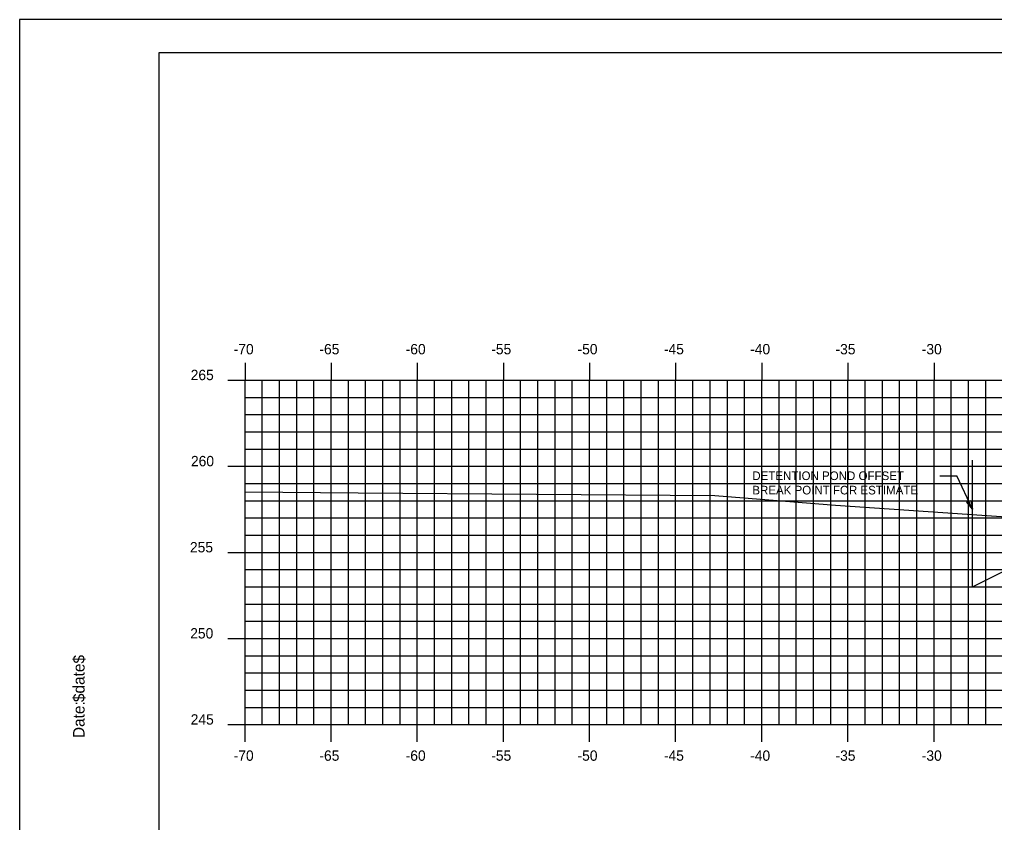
# Model space of a CAD drawing. Extents: x 1160718 to 1173142, y 616002 to 617630.
# Drawn here: x 1170766.3 to 1170822.9, y 616677.2 to 616723.9 of the extents above; entities that cross this region are included whole.
import ezdxf

# ---------------------------------------------------------------- set-up
doc = ezdxf.new("R2010")
doc.units = 0
for name, color, linetype in [('ANNOTATION', 7, 'Continuous'), ('BORDER', 7, 'Continuous'), ('D_Roadway_Centerline', 7, 'Continuous'), ('D_Roadway_Edge_Pavement', 7, 'Continuous'), ('D_Roadway_Edge_TW', 7, 'Continuous'), ('D_Roadway_Pavement', 7, 'Continuous'), ('H_V ANNOTATION', 7, 'Continuous'), ('MAJOR', 7, 'Continuous'), ('MINOR', 7, 'Continuous'), ('PLOT BOUNDARY', 7, 'Continuous'), ('S_Roadway_Centerline', 7, 'Continuous')]:
    doc.layers.add(name, color=color, linetype=linetype)

msp = doc.modelspace()

# ---------------------------------------------------------------- linework, layer by layer
at = {"layer": 'ANNOTATION'}
for p in [(1170819.751, 616697.377), (1170821.653, 616695.436)]:
    msp.add_line(p, (1170820.751, 616697.377), dxfattribs=at)
msp.add_lwpolyline([(1170821.556, 616695.942), (1170821.653, 616695.436), (1170821.329, 616695.837)], close=True, dxfattribs=at)
at = {"layer": 'BORDER'}
for p, q in [((1170934.42, 616721.928), (1170774.42, 616721.928)), ((1170774.42, 616721.928), (1170774.42, 616616.928))]:
    msp.add_line(p, q, dxfattribs=at)
at = {"layer": 'D_Roadway_Centerline'}
msp.add_lwpolyline([(1170821.653, 616690.928), (1170830.356, 616695.28)], dxfattribs=at)
at = {"layer": 'D_Roadway_Edge_Pavement'}
msp.add_lwpolyline([(1170779.42, 616690.928), (1170814.248, 616690.928), (1170821.653, 616690.928)], dxfattribs=at)
at = {"layer": 'D_Roadway_Edge_TW'}
msp.add_line((1170779.42, 616690.928), (1170821.653, 616690.928), dxfattribs=at)
at = {"layer": 'D_Roadway_Pavement'}
msp.add_line((1170821.653, 616690.928), (1170821.653, 616698.285), dxfattribs=at)
at = {"layer": 'MAJOR'}
for p, q in [((1170779.42, 616703.93), (1170779.42, 616702.928)), ((1170784.42, 616703.93), (1170784.42, 616702.928)), ((1170789.42, 616703.93), (1170789.42, 616702.928)), ((1170794.42, 616703.93), (1170794.42, 616702.928)), ((1170799.42, 616703.93), (1170799.42, 616702.928)), ((1170804.42, 616703.93), (1170804.42, 616702.928)), ((1170809.42, 616703.93), (1170809.42, 616702.928)), ((1170814.42, 616703.93), (1170814.42, 616702.928)), ((1170819.42, 616703.93), (1170819.42, 616702.928)), ((1170778.418, 616702.928), (1170779.42, 616702.928)), ((1170779.42, 616702.928), (1170919.42, 616702.928)), ((1170779.42, 616682.928), (1170779.42, 616702.928)), ((1170779.42, 616682.928), (1170779.42, 616702.928)), ((1170779.42, 616702.928), (1170919.42, 616702.928)), ((1170784.42, 616682.928), (1170784.42, 616702.928)), ((1170789.42, 616682.928), (1170789.42, 616702.928)), ((1170794.42, 616682.928), (1170794.42, 616702.928)), ((1170799.42, 616682.928), (1170799.42, 616702.928)), ((1170804.42, 616682.928), (1170804.42, 616702.928)), ((1170809.42, 616682.928), (1170809.42, 616702.928)), ((1170814.42, 616682.928), (1170814.42, 616702.928)), ((1170819.42, 616682.928), (1170819.42, 616702.928)), ((1170778.418, 616697.928), (1170779.42, 616697.928)), ((1170779.42, 616697.928), (1170919.42, 616697.928)), ((1170778.418, 616692.928), (1170779.42, 616692.928)), ((1170779.42, 616692.928), (1170919.42, 616692.928)), ((1170778.418, 616687.928), (1170779.42, 616687.928)), ((1170779.42, 616687.928), (1170919.42, 616687.928)), ((1170778.418, 616682.928), (1170779.42, 616682.928)), ((1170779.42, 616682.928), (1170919.42, 616682.928)), ((1170779.42, 616682.928), (1170919.42, 616682.928)), ((1170779.42, 616681.926), (1170779.42, 616682.928)), ((1170784.42, 616681.926), (1170784.42, 616682.928)), ((1170789.42, 616681.926), (1170789.42, 616682.928)), ((1170794.42, 616681.926), (1170794.42, 616682.928)), ((1170799.42, 616681.926), (1170799.42, 616682.928)), ((1170804.42, 616681.926), (1170804.42, 616682.928)), ((1170809.42, 616681.926), (1170809.42, 616682.928)), ((1170814.42, 616681.926), (1170814.42, 616682.928)), ((1170819.42, 616681.926), (1170819.42, 616682.928))]:
    msp.add_line(p, q, dxfattribs=at)
at = {"layer": 'MINOR'}
for p, q in [((1170780.42, 616682.928), (1170780.42, 616702.928)), ((1170781.42, 616682.928), (1170781.42, 616702.928)), ((1170782.42, 616682.928), (1170782.42, 616702.928)), ((1170783.42, 616682.928), (1170783.42, 616702.928)), ((1170785.42, 616682.928), (1170785.42, 616702.928)), ((1170786.42, 616682.928), (1170786.42, 616702.928)), ((1170787.42, 616682.928), (1170787.42, 616702.928)), ((1170788.42, 616682.928), (1170788.42, 616702.928)), ((1170790.42, 616682.928), (1170790.42, 616702.928)), ((1170791.42, 616682.928), (1170791.42, 616702.928)), ((1170792.42, 616682.928), (1170792.42, 616702.928)), ((1170793.42, 616682.928), (1170793.42, 616702.928)), ((1170795.42, 616682.928), (1170795.42, 616702.928)), ((1170796.42, 616682.928), (1170796.42, 616702.928)), ((1170797.42, 616682.928), (1170797.42, 616702.928)), ((1170798.42, 616682.928), (1170798.42, 616702.928)), ((1170800.42, 616682.928), (1170800.42, 616702.928)), ((1170801.42, 616682.928), (1170801.42, 616702.928)), ((1170802.42, 616682.928), (1170802.42, 616702.928)), ((1170803.42, 616682.928), (1170803.42, 616702.928)), ((1170805.42, 616682.928), (1170805.42, 616702.928)), ((1170806.42, 616682.928), (1170806.42, 616702.928)), ((1170807.42, 616682.928), (1170807.42, 616702.928)), ((1170808.42, 616682.928), (1170808.42, 616702.928)), ((1170810.42, 616682.928), (1170810.42, 616702.928)), ((1170811.42, 616682.928), (1170811.42, 616702.928)), ((1170812.42, 616682.928), (1170812.42, 616702.928)), ((1170813.42, 616682.928), (1170813.42, 616702.928)), ((1170815.42, 616682.928), (1170815.42, 616702.928)), ((1170816.42, 616682.928), (1170816.42, 616702.928)), ((1170817.42, 616682.928), (1170817.42, 616702.928)), ((1170818.42, 616682.928), (1170818.42, 616702.928)), ((1170820.42, 616682.928), (1170820.42, 616702.928)), ((1170821.42, 616682.928), (1170821.42, 616702.928)), ((1170822.42, 616682.928), (1170822.42, 616702.928)), ((1170779.42, 616701.928), (1170919.42, 616701.928)), ((1170779.42, 616701.928), (1170780.422, 616701.928)), ((1170779.42, 616700.928), (1170919.42, 616700.928)), ((1170779.42, 616700.928), (1170780.422, 616700.928)), ((1170779.42, 616699.928), (1170919.42, 616699.928)), ((1170779.42, 616699.928), (1170780.422, 616699.928)), ((1170779.42, 616698.928), (1170919.42, 616698.928)), ((1170779.42, 616698.928), (1170780.422, 616698.928)), ((1170779.42, 616696.928), (1170919.42, 616696.928)), ((1170779.42, 616696.928), (1170780.422, 616696.928)), ((1170779.42, 616695.928), (1170919.42, 616695.928)), ((1170779.42, 616695.928), (1170780.422, 616695.928)), ((1170779.42, 616694.928), (1170919.42, 616694.928)), ((1170779.42, 616694.928), (1170780.422, 616694.928)), ((1170779.42, 616693.928), (1170919.42, 616693.928)), ((1170779.42, 616693.928), (1170780.422, 616693.928)), ((1170779.42, 616691.928), (1170919.42, 616691.928)), ((1170779.42, 616691.928), (1170780.422, 616691.928)), ((1170779.42, 616690.928), (1170919.42, 616690.928)), ((1170779.42, 616690.928), (1170780.422, 616690.928)), ((1170779.42, 616689.928), (1170919.42, 616689.928)), ((1170779.42, 616689.928), (1170780.422, 616689.928)), ((1170779.42, 616688.928), (1170919.42, 616688.928)), ((1170779.42, 616688.928), (1170780.422, 616688.928)), ((1170779.42, 616686.928), (1170919.42, 616686.928)), ((1170779.42, 616686.928), (1170780.422, 616686.928)), ((1170779.42, 616685.928), (1170919.42, 616685.928)), ((1170779.42, 616685.928), (1170780.422, 616685.928)), ((1170779.42, 616684.928), (1170919.42, 616684.928)), ((1170779.42, 616684.928), (1170780.422, 616684.928)), ((1170779.42, 616683.928), (1170919.42, 616683.928)), ((1170779.42, 616683.928), (1170780.422, 616683.928))]:
    msp.add_line(p, q, dxfattribs=at)
at = {"layer": 'PLOT BOUNDARY'}
msp.add_lwpolyline([(1170766.327, 616613.869), (1170936.327, 616613.869), (1170936.327, 616723.869), (1170766.327, 616723.869)], close=True, dxfattribs=at)
at = {"layer": 'S_Roadway_Centerline'}
msp.add_lwpolyline([(1170779.42, 616696.44), (1170785.984, 616696.378), (1170806.69, 616696.234), (1170813.698, 616695.667), (1170833.797, 616694.287), (1170838.103, 616693.884), (1170847.001, 616692.856), (1170850.454, 616693.286), (1170860.01, 616695.499), (1170861.382, 616695.753), (1170862.017, 616695.889), (1170862.551, 616696.007), (1170864.828, 616696.132), (1170865.614, 616696.172), (1170866.95, 616696.208), (1170870.653, 616696.303), (1170871.434, 616696.318), (1170875.691, 616696.397), (1170875.917, 616696.399), (1170877.736, 616696.418)], dxfattribs=at)

# ---------------------------------------------------------------- texts
at = {"layer": 'ANNOTATION'}
for s, p in [('DETENTION POND OFFSET', (1170808.87, 616697.127)), ('BREAK POINT FOR ESTIMATE', (1170808.87, 616696.292))]:
    msp.add_text(s, height=0.5, dxfattribs=at).set_placement(p)
at = {"layer": 'BORDER'}
for s, p in [('$date$', (1170770.105, 616684.234)), ('Date:', (1170770.105, 616682.145))]:
    msp.add_text(s, height=0.6696, rotation=90, dxfattribs=at).set_placement(p)
at = {"layer": 'H_V ANNOTATION'}
for s, p in [('-70', (1170778.762, 616704.428)), ('-65', (1170783.738, 616704.428)), ('-60', (1170788.746, 616704.428)), ('-55', (1170793.716, 616704.428)), ('-50', (1170798.724, 616704.428)), ('-45', (1170803.738, 616704.428)), ('-40', (1170808.746, 616704.428)), ('-35', (1170813.7, 616704.428)), ('-30', (1170818.708, 616704.428)), ('265', (1170776.266, 616702.928)), ('260', (1170776.282, 616697.928)), ('255', (1170776.223, 616692.928)), ('250', (1170776.239, 616687.928)), ('245', (1170776.266, 616682.928)), ('-70', (1170778.762, 616680.828)), ('-65', (1170783.738, 616680.828)), ('-60', (1170788.746, 616680.828)), ('-55', (1170793.716, 616680.828)), ('-50', (1170798.724, 616680.828)), ('-45', (1170803.738, 616680.828)), ('-40', (1170808.746, 616680.828)), ('-35', (1170813.7, 616680.828)), ('-30', (1170818.708, 616680.828))]:
    msp.add_text(s, height=0.6, dxfattribs=at).set_placement(p)

doc.saveas('drawing.dxf')
